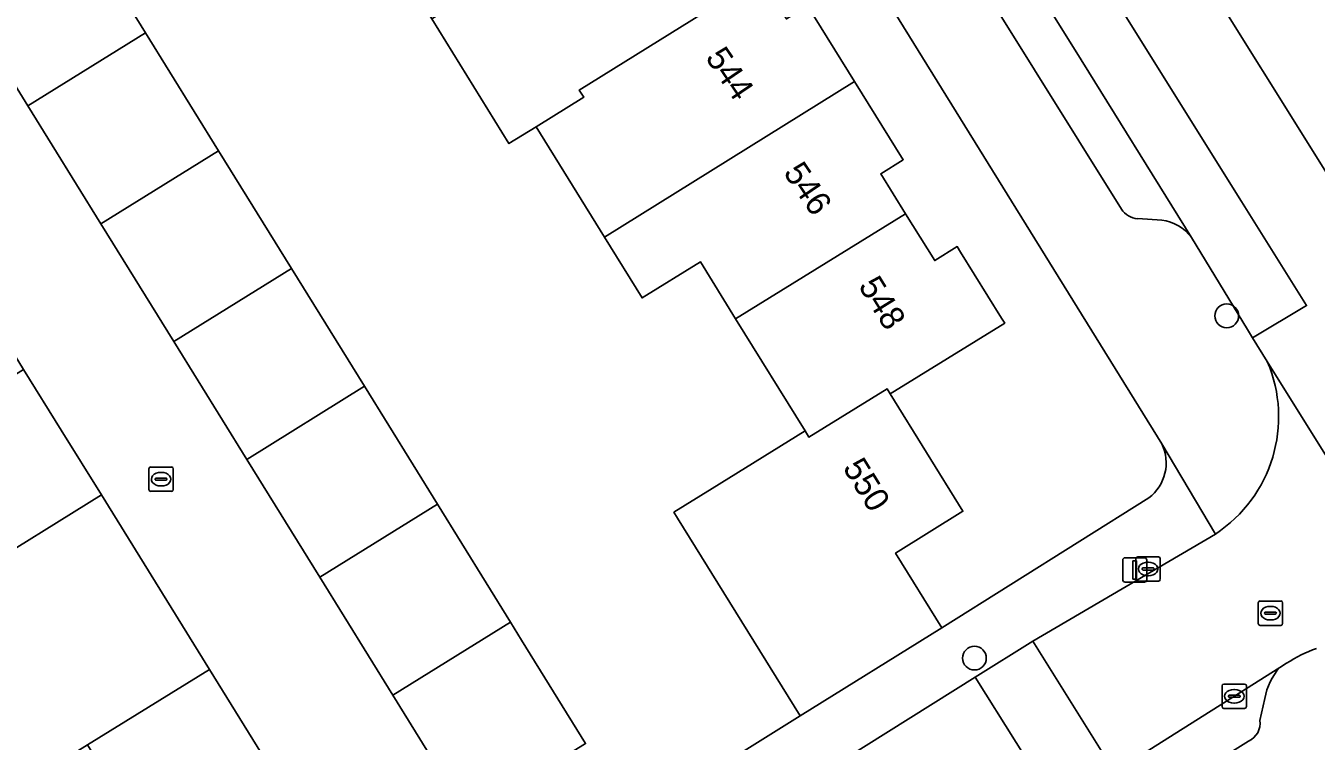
# Model space of a CAD drawing. Extents: x 157767 to 159172, y 387839 to 389425.
# Drawn here: x 158532 to 158585.1, y 388208.2 to 388237.6 of the extents above; entities that cross this region are included whole.
import ezdxf

# ---------------------------------------------------------------- set-up
doc = ezdxf.new("R2010")
doc.units = 0
for name, color, linetype in [('IMGEO_Berm_groen', 7, 'Continuous'), ('IMGEO_Boom', 7, 'Continuous'), ('IMGEO_Erf', 7, 'Continuous'), ('IMGEO_Kolk', 7, 'Continuous'), ('IMGEO_Lichtmast', 7, 'Continuous'), ('IMGEO_Muur', 7, 'Continuous'), ('IMGEO_Pand', 7, 'Continuous'), ('IMGEO_Pand_nummerreeks', 7, 'Continuous'), ('IMGEO_Parkeervlak_open', 7, 'Continuous'), ('IMGEO_Rijbaan_lokaal_gesloten', 7, 'Continuous'), ('IMGEO_Rijbaan_lokaal_open', 7, 'Continuous'), ('IMGEO_Rioolput', 7, 'Continuous'), ('IMGEO_Voetpad_open', 7, 'Continuous')]:
    doc.layers.add(name, color=color, linetype=linetype)

msp = doc.modelspace()

# ---------------------------------------------------------------- linework, layer by layer
at = {"layer": 'IMGEO_Berm_groen'}
msp.add_lwpolyline([(158564.255, 388265.206), (158565.51, 388263.197), (158573.752, 388250), (158577.332, 388244.667), (158588.346, 388227.053), (158588.442, 388226.901)], dxfattribs=at)
at = {"layer": 'IMGEO_Boom'}
for centre in [(158581.402, 388225.717), (158571.026, 388211.65)]:
    msp.add_circle(centre, 0.489, dxfattribs=at)
at = {"layer": 'IMGEO_Erf'}
for points in [[(158578.731, 388220.462), (158560.433, 388250)], [(158553.311, 388202.687), (158563.857, 388209.275), (158558.819, 388217.407), (158558.671, 388217.647), (158560.246, 388218.623), (158564.061, 388220.986), (158561.207, 388225.594), (158559.755, 388227.937), (158557.36, 388226.453), (158555.814, 388228.948), (158553.002, 388233.489), (158551.885, 388232.797), (158548.706, 388237.927), (158545.703, 388242.774), (158542.091, 388248.605), (158528.549, 388240.047)], [(158529.077, 388239.236), (158533.328, 388241.87), (158533.915, 388242.233), (158536.942, 388237.347), (158539.942, 388232.504), (158542.941, 388227.664), (158545.941, 388222.82), (158548.946, 388217.97), (158551.947, 388213.126), (158552.404, 388212.388), (158555.037, 388208.137)], [(158564.168, 388238.461), (158566.099, 388235.354), (158568.101, 388232.131), (158567.175, 388231.556), (158568.196, 388229.913), (158569.392, 388227.988), (158570.318, 388228.564), (158570.457, 388228.34), (158572.144, 388225.624), (158572.27, 388225.421), (158567.565, 388222.507), (158570.554, 388217.682), (158567.782, 388215.966), (158569.689, 388212.888), (158578.194, 388218.231)], [(158524.872, 388202.081), (158529.71, 388205.078), (158534.555, 388208.08), (158539.565, 388211.183), (158535.121, 388218.358), (158529.777, 388215.048), (158528.132, 388217.703), (158526.583, 388220.204), (158525.078, 388222.633), (158519.119, 388218.831), (158520.036, 388217.36), (158516.701, 388215.281), (158518.695, 388212.062), (158516.652, 388210.796), (158514.657, 388214.015), (158513.115, 388213.053), (158512.201, 388214.518), (158509.533, 388212.894), (158511.102, 388210.362), (158507.634, 388208.213), (158502.303, 388204.91)]]:
    msp.add_lwpolyline(points, dxfattribs=at)
msp.add_arc((158577.113, 388219.671), 1.8, 306.8788, 26.054, dxfattribs=at)
at = {"layer": 'IMGEO_Kolk'}
for p, q in [((158537.077, 388218.578), (158537.077, 388219.43)), ((158537.152, 388219.504), (158538.004, 388219.504)), ((158537.379, 388219.047), (158537.777, 388219.047)), ((158537.565, 388219.284), (158537.59, 388219.284)), ((158538.078, 388219.43), (158538.078, 388218.578)), ((158538.004, 388218.504), (158537.152, 388218.504)), ((158537.336, 388218.998), (158537.336, 388219.01)), ((158537.774, 388218.961), (158537.376, 388218.961)), ((158537.588, 388218.724), (158537.563, 388218.724)), ((158537.82, 388219.01), (158537.82, 388218.998)), ((158577.669, 388214.887), (158577.669, 388215.739)), ((158577.744, 388215.813), (158578.596, 388215.813)), ((158577.928, 388215.307), (158577.928, 388215.319)), ((158577.971, 388215.356), (158578.369, 388215.356)), ((158578.157, 388215.593), (158578.182, 388215.593)), ((158578.412, 388215.319), (158578.412, 388215.307)), ((158578.67, 388215.739), (158578.67, 388214.887)), ((158578.596, 388214.813), (158577.744, 388214.813)), ((158578.366, 388215.27), (158577.968, 388215.27)), ((158578.18, 388215.033), (158578.155, 388215.033)), ((158581.287, 388210.581), (158582.139, 388210.581)), ((158581.212, 388209.655), (158581.212, 388210.507)), ((158581.471, 388210.075), (158581.471, 388210.087)), ((158581.909, 388210.038), (158581.511, 388210.038)), ((158581.514, 388210.124), (158581.912, 388210.124)), ((158581.7, 388210.361), (158581.725, 388210.361)), ((158581.955, 388210.087), (158581.955, 388210.075)), ((158582.213, 388210.507), (158582.213, 388209.655)), ((158582.139, 388209.581), (158581.287, 388209.581)), ((158581.723, 388209.801), (158581.698, 388209.801))]:
    msp.add_line(p, q, dxfattribs=at)
for points in [[(158537.077, 388218.578), (158537.077, 388219.43)], [(158537.152, 388219.504), (158538.004, 388219.504)], [(158538.078, 388219.43), (158538.078, 388218.578)], [(158538.004, 388218.504), (158537.152, 388218.504)], [(158577.669, 388214.887), (158577.669, 388215.739)], [(158577.744, 388215.813), (158578.596, 388215.813)], [(158578.67, 388215.739), (158578.67, 388214.887)], [(158578.596, 388214.813), (158577.744, 388214.813)], [(158581.287, 388210.581), (158582.139, 388210.581)], [(158581.212, 388209.655), (158581.212, 388210.507)], [(158582.213, 388210.507), (158582.213, 388209.655)], [(158582.139, 388209.581), (158581.287, 388209.581)]]:
    msp.add_lwpolyline(points, dxfattribs=at)
for centre, radius, start, end in [((158537.154, 388219.428), 0.0765, 91.552, 178.448), ((158537.154, 388219.428), 0.0765, 91.552, 178.448), ((158537.376, 388219.007), 0.0403, 85.8775, 175.7526), ((158537.781, 388219.009), 0.0386, 1.7309, 96.639), ((158538.002, 388219.428), 0.0765, 1.552, 88.448), ((158538.002, 388219.428), 0.0765, 1.552, 88.448), ((158537.154, 388218.58), 0.0765, 181.552, 268.448), ((158537.154, 388218.58), 0.0765, 181.552, 268.448), ((158537.373, 388218.997), 0.0366, 178.938, 274.7102), ((158537.777, 388219.004), 0.043, 264.8664, 352.4533), ((158538.002, 388218.58), 0.0765, 271.552, 358.448), ((158538.002, 388218.58), 0.0765, 271.552, 358.448), ((158577.746, 388215.737), 0.0765, 91.552, 178.448), ((158577.746, 388215.737), 0.0765, 91.552, 178.448), ((158577.968, 388215.316), 0.0403, 85.8775, 175.7526), ((158577.965, 388215.306), 0.0366, 178.938, 274.7102), ((158578.369, 388215.313), 0.043, 264.8664, 352.4533), ((158578.373, 388215.318), 0.0386, 1.7309, 96.639), ((158578.594, 388215.737), 0.0765, 1.552, 88.448), ((158578.594, 388215.737), 0.0765, 1.552, 88.448), ((158577.746, 388214.889), 0.0765, 181.552, 268.448), ((158577.746, 388214.889), 0.0765, 181.552, 268.448), ((158578.594, 388214.889), 0.0765, 271.552, 358.448), ((158578.594, 388214.889), 0.0765, 271.552, 358.448), ((158581.289, 388210.505), 0.0765, 91.552, 178.448), ((158581.289, 388210.505), 0.0765, 91.552, 178.448), ((158582.137, 388210.505), 0.0765, 1.552, 88.448), ((158582.137, 388210.505), 0.0765, 1.552, 88.448), ((158581.511, 388210.084), 0.0403, 85.8775, 175.7526), ((158581.508, 388210.074), 0.0366, 178.938, 274.7102), ((158581.912, 388210.081), 0.043, 264.8664, 352.4533), ((158581.916, 388210.086), 0.0386, 1.7309, 96.639), ((158581.289, 388209.657), 0.0765, 181.552, 268.448), ((158581.289, 388209.657), 0.0765, 181.552, 268.448), ((158582.137, 388209.657), 0.0765, 271.552, 358.448), ((158582.137, 388209.657), 0.0765, 271.552, 358.448)]:
    msp.add_arc(centre, radius, start, end, dxfattribs=at)
for centre, major_axis, ratio, start_param, end_param in [((158537.564, 388219.004), (-0.387, 0.002), 0.722429, 4.712389, 7.853982), ((158537.589, 388219.004), (-0.39, 0.002), 0.717154, 1.570796, 4.712389), ((158578.156, 388215.313), (-0.387, 0.002), 0.722429, 4.712389, 7.853982), ((158578.181, 388215.313), (-0.39, 0.002), 0.717154, 1.570796, 4.712389), ((158581.699, 388210.081), (-0.387, 0.002), 0.722429, 4.712389, 7.853982), ((158581.724, 388210.081), (-0.39, 0.002), 0.717154, 1.570796, 4.712389)]:
    msp.add_ellipse(centre, major_axis=major_axis, ratio=ratio, start_param=start_param, end_param=end_param, dxfattribs=at)
at = {"layer": 'IMGEO_Lichtmast'}
for p, q in [((158577.124, 388214.872), (158577.124, 388215.672)), ((158577.124, 388215.672), (158577.124, 388214.872)), ((158577.224, 388215.772), (158578.014, 388215.772)), ((158578.014, 388215.772), (158577.224, 388215.772)), ((158578.114, 388215.672), (158578.114, 388214.872)), ((158578.114, 388214.872), (158578.114, 388215.672)), ((158578.014, 388214.772), (158577.224, 388214.772)), ((158577.224, 388214.772), (158578.014, 388214.772))]:
    msp.add_line(p, q, dxfattribs=at)
msp.add_lwpolyline([(158577.544, 388215.647), (158577.694, 388215.647), (158577.694, 388214.897), (158577.544, 388214.897), (158577.544, 388215.647)], dxfattribs=at)
for centre, start, end in [((158577.224, 388215.672), 90, 180), ((158577.224, 388215.672), 90, 180), ((158578.014, 388215.672), 0, 90), ((158578.014, 388215.672), 360, 90), ((158577.224, 388214.872), 180, 270), ((158577.224, 388214.872), 180, 270), ((158578.014, 388214.872), 270, 0), ((158578.014, 388214.872), 270, 0)]:
    msp.add_arc(centre, 0.1, start, end, dxfattribs=at)
at = {"layer": 'IMGEO_Muur'}
for points in [[(158535.121, 388218.358), (158539.565, 388211.183)], [(158552.418, 388204.082), (158553.311, 388202.687), (158563.857, 388209.275)]]:
    msp.add_lwpolyline(points, dxfattribs=at)
at = {"layer": 'IMGEO_Pand'}
for points in [[(158562.223, 388239.643), (158562.059, 388239.907), (158561.656, 388239.657), (158561.002, 388240.713), (158561.634, 388241.107), (158561.88, 388242.078), (158560.077, 388244.99), (158551.779, 388239.832), (158548.706, 388237.927), (158551.885, 388232.797), (158553.002, 388233.489), (158554.958, 388234.701), (158554.774, 388234.999)], [(158532.103, 388234.351), (158536.942, 388237.347), (158533.915, 388242.233), (158533.328, 388241.87), (158529.077, 388239.236)], [(158554.774, 388234.999), (158554.958, 388234.701), (158553.002, 388233.489), (158555.814, 388228.948), (158566.099, 388235.354), (158564.168, 388238.461), (158563.291, 388237.918), (158562.223, 388239.643)], [(158539.942, 388232.504), (158536.942, 388237.347), (158532.103, 388234.351), (158535.105, 388229.505)], [(158561.207, 388225.594), (158568.196, 388229.913), (158567.175, 388231.556), (158568.101, 388232.131), (158566.099, 388235.354), (158555.814, 388228.948), (158557.36, 388226.453), (158559.755, 388227.937)], [(158538.106, 388224.66), (158542.941, 388227.664), (158539.942, 388232.504), (158535.105, 388229.505)], [(158572.27, 388225.421), (158572.144, 388225.624), (158570.457, 388228.34), (158570.318, 388228.564), (158569.392, 388227.988), (158568.196, 388229.913), (158561.207, 388225.594), (158564.061, 388220.986), (158564.216, 388220.735), (158567.433, 388222.719), (158567.565, 388222.507)], [(158538.106, 388224.66), (158541.108, 388219.815), (158545.941, 388222.82), (158542.941, 388227.664)], [(158526.583, 388220.204), (158528.132, 388217.703), (158529.777, 388215.048), (158535.121, 388218.358), (158533.474, 388221.012), (158531.925, 388223.513)], [(158548.946, 388217.97), (158545.941, 388222.82), (158541.108, 388219.815), (158544.11, 388214.97)], [(158567.565, 388222.507), (158567.433, 388222.719), (158564.216, 388220.735), (158564.061, 388220.986), (158560.246, 388218.623), (158558.671, 388217.647), (158558.819, 388217.407), (158563.857, 388209.275), (158569.689, 388212.888), (158567.782, 388215.966), (158570.554, 388217.682)], [(158548.946, 388217.97), (158544.11, 388214.97), (158547.114, 388210.12), (158551.947, 388213.126)], [(158551.947, 388213.126), (158547.114, 388210.12), (158550.199, 388205.14), (158551.302, 388205.823), (158555.037, 388208.137), (158552.404, 388212.388)], [(158534.555, 388208.08), (158539.217, 388200.612), (158544.201, 388203.7), (158539.565, 388211.183)]]:
    msp.add_lwpolyline(points, close=True, dxfattribs=at)
at = {"layer": 'IMGEO_Parkeervlak_open'}
for points in [[(158579.948, 388228.937), (158575.174, 388236.636), (158566.803, 388250), (158546.8, 388282.11), (158545.84, 388283.885), (158541.357, 388292.498)], [(158541.037, 388289.104), (158544.279, 388283.073), (158545.212, 388281.281), (158558.949, 388259.176), (158564.652, 388250), (158577.077, 388230.108)], [(158577.742, 388229.711), (158578.731, 388229.648)], [(158583.586, 388211.261), (158576.785, 388206.98), (158574.424, 388205.494), (158559.548, 388196.131), (158554.555, 388193.003)], [(158582.765, 388209.088), (158582.975, 388209.991)], [(158557.621, 388192.85), (158582.301, 388208.235)]]:
    msp.add_lwpolyline(points, dxfattribs=at)
for centre, radius, start, end in [((158577.797, 388230.558), 0.849, 212.0236, 266.3027), ((158578.515, 388227.881), 1.78, 36.3842, 83.0268), ((158585.39, 388209.611), 2.445, 137.554, 171.0614), ((158581.968, 388208.969), 0.806, 294.4132, 8.4977)]:
    msp.add_arc(centre, radius, start, end, dxfattribs=at)
at = {"layer": 'IMGEO_Rijbaan_lokaal_gesloten'}
for points in [[(158543.772, 388291.077), (158540.051, 388296.6), (158538.816, 388298.433), (158537.124, 388300.9), (158541.209, 388292.781), (158541.357, 388292.498), (158545.84, 388283.885), (158546.8, 388282.11), (158566.803, 388250), (158575.174, 388236.636), (158579.948, 388228.937), (158582.25, 388225.149), (158582.462, 388224.809), (158584.684, 388226.139), (158582.01, 388230.413), (158562.62, 388261.425), (158561.929, 388262.53), (158548.944, 388283.404)], [(158617.332, 388180.649), (158611.001, 388190.832), (158604.502, 388201.086), (158600.639, 388207.182), (158599.628, 388208.979), (158597.392, 388212.554), (158596.27, 388214.348), (158588.442, 388226.901), (158588.346, 388227.053), (158577.332, 388244.667), (158573.752, 388250), (158565.51, 388263.197), (158562.62, 388261.425), (158582.01, 388230.413), (158584.684, 388226.139), (158582.462, 388224.809), (158583.071, 388223.836), (158590.939, 388211.246), (158593.162, 388212.593), (158602.586, 388197.444), (158620.732, 388168.245), (158626.043, 388159.864), (158629.046, 388161.861), (158622.142, 388172.911)]]:
    msp.add_lwpolyline(points, close=True, dxfattribs=at)
at = {"layer": 'IMGEO_Rijbaan_lokaal_open'}
for points in [[(158550.199, 388205.14), (158547.114, 388210.12), (158544.11, 388214.97), (158541.108, 388219.815), (158538.106, 388224.66), (158535.105, 388229.505), (158532.103, 388234.351), (158529.077, 388239.236), (158528.549, 388240.047), (158527.662, 388241.411), (158526.344, 388240.622), (158525.848, 388241.522), (158522.786, 388246.465), (158520.596, 388250), (158519.793, 388251.296), (158516.767, 388256.181), (158513.747, 388261.055), (158510.76, 388265.877), (158507.701, 388270.816)], [(158503.231, 388264.672), (158506.175, 388259.964), (158509.482, 388256.507), (158510.057, 388255.619), (158513.039, 388250.805), (158513.538, 388250), (158516.041, 388245.959), (158519.054, 388241.095), (158522.06, 388236.243), (158525.074, 388231.378), (158528.16, 388226.396), (158528.963, 388225.039), (158530.42, 388225.942), (158531.925, 388223.513), (158533.474, 388221.012), (158535.121, 388218.358), (158539.565, 388211.183), (158544.201, 388203.7)], [(158591.586, 388210.211), (158590.939, 388211.246), (158583.071, 388223.836)], [(158580.934, 388216.749), (158573.427, 388212.344), (158576.785, 388206.98), (158583.586, 388211.261), (158583.866, 388211.437)]]:
    msp.add_lwpolyline(points, dxfattribs=at)
for points in [[(158571.062, 388210.864), (158574.424, 388205.494), (158576.785, 388206.98), (158573.427, 388212.344)], [(158559.548, 388196.131), (158574.424, 388205.494), (158571.062, 388210.864), (158554.629, 388200.581), (158554.338, 388200.399), (158550.005, 388197.688), (158549.549, 388197.402), (158549.435, 388197.331), (158527.044, 388183.328), (158530.44, 388177.896), (158549.763, 388190.001), (158553.753, 388192.501), (158554.555, 388193.003)]]:
    msp.add_lwpolyline(points, close=True, dxfattribs=at)
for centre, radius, start, end in [((158577.777, 388221.567), 5.76, 303.2389, 23.201), ((158587.039, 388206.575), 5.806, 109.5533, 123.1287)]:
    msp.add_arc(centre, radius, start, end, dxfattribs=at)
at = {"layer": 'IMGEO_Rioolput'}
for p, q in [((158582.701, 388213.07), (158582.701, 388213.922)), ((158582.776, 388213.996), (158583.628, 388213.996)), ((158583.189, 388213.776), (158583.214, 388213.776)), ((158583.702, 388213.922), (158583.702, 388213.07)), ((158582.96, 388213.49), (158582.96, 388213.502)), ((158583.398, 388213.453), (158583, 388213.453)), ((158583.003, 388213.539), (158583.401, 388213.539)), ((158583.212, 388213.216), (158583.187, 388213.216)), ((158583.444, 388213.502), (158583.444, 388213.49)), ((158583.628, 388212.996), (158582.776, 388212.996))]:
    msp.add_line(p, q, dxfattribs=at)
for points in [[(158582.701, 388213.07), (158582.701, 388213.922)], [(158582.776, 388213.996), (158583.628, 388213.996)], [(158583.702, 388213.922), (158583.702, 388213.07)], [(158583.628, 388212.996), (158582.776, 388212.996)]]:
    msp.add_lwpolyline(points, dxfattribs=at)
for centre, radius, start, end in [((158582.778, 388213.92), 0.0765, 91.552, 178.448), ((158582.778, 388213.92), 0.0765, 91.552, 178.448), ((158583.626, 388213.92), 0.0765, 1.552, 88.448), ((158583.626, 388213.92), 0.0765, 1.552, 88.448), ((158583, 388213.499), 0.0403, 85.8775, 175.7526), ((158582.997, 388213.489), 0.0366, 178.938, 274.7102), ((158583.401, 388213.496), 0.043, 264.8664, 352.4533), ((158583.405, 388213.501), 0.0386, 1.7309, 96.639), ((158582.778, 388213.072), 0.0765, 181.552, 268.448), ((158582.778, 388213.072), 0.0765, 181.552, 268.448), ((158583.626, 388213.072), 0.0765, 271.552, 358.448), ((158583.626, 388213.072), 0.0765, 271.552, 358.448)]:
    msp.add_arc(centre, radius, start, end, dxfattribs=at)
for centre, major_axis, ratio, start_param, end_param in [((158583.188, 388213.496), (-0.387, 0.002), 0.722429, 4.712389, 7.853982), ((158583.213, 388213.496), (-0.39, 0.002), 0.717154, 1.570796, 4.712389)]:
    msp.add_ellipse(centre, major_axis=major_axis, ratio=ratio, start_param=start_param, end_param=end_param, dxfattribs=at)
at = {"layer": 'IMGEO_Voetpad_open'}
for points in [[(158541.357, 388292.498), (158541.209, 388292.781), (158540.782, 388292.516), (158536.64, 388289.939), (158535.956, 388289.514), (158555.243, 388258.379), (158555.904, 388257.311), (158555.974, 388257.198), (158560.433, 388250), (158578.731, 388220.462), (158580.934, 388216.749)], [(158577.077, 388230.108), (158564.652, 388250), (158558.949, 388259.176)], [(158578.731, 388229.648), (158577.742, 388229.711)], [(158583.071, 388223.836), (158582.462, 388224.809), (158582.25, 388225.149), (158579.948, 388228.937)], [(158571.062, 388210.864), (158573.427, 388212.344), (158580.934, 388216.749), (158578.731, 388220.462)], [(158578.194, 388218.231), (158569.689, 388212.888), (158563.857, 388209.275), (158553.311, 388202.687), (158554.629, 388200.581), (158571.062, 388210.864)], [(158583.866, 388211.437), (158583.586, 388211.261)], [(158582.975, 388209.991), (158582.765, 388209.088)], [(158582.301, 388208.235), (158557.621, 388192.85)]]:
    msp.add_lwpolyline(points, dxfattribs=at)
for centre, radius, start, end in [((158577.797, 388230.558), 0.849, 212.0236, 266.3027), ((158578.515, 388227.881), 1.78, 36.3842, 83.0268), ((158577.777, 388221.567), 5.76, 303.2389, 23.201), ((158577.113, 388219.671), 1.8, 306.8788, 26.054), ((158587.039, 388206.575), 5.806, 109.5533, 123.1287), ((158585.39, 388209.611), 2.445, 137.554, 171.0614), ((158581.968, 388208.969), 0.806, 294.4132, 8.4977)]:
    msp.add_arc(centre, radius, start, end, dxfattribs=at)

# ---------------------------------------------------------------- texts
at = {"layer": 'IMGEO_Pand_nummerreeks'}
for s, rotation, p in [('544', 304.156, (158559.936, 388236.327)), ('546', 304.156, (158563.143, 388231.6)), ('548', 301.7818, (158566.23, 388226.946)), ('550', 301.7818, (158565.587, 388219.472))]:
    msp.add_text(s, height=1, rotation=rotation, dxfattribs=at).set_placement(p)

doc.saveas('drawing.dxf')
